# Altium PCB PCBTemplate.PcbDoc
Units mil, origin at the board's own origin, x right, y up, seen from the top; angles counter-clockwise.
Board outline 6000 x 4000 mil, 4 copper layers (Top Layer, Internal Plane 1, Internal Plane 2, Bottom Layer); 0 components, 0 nets, 1 pads, 0 vias.
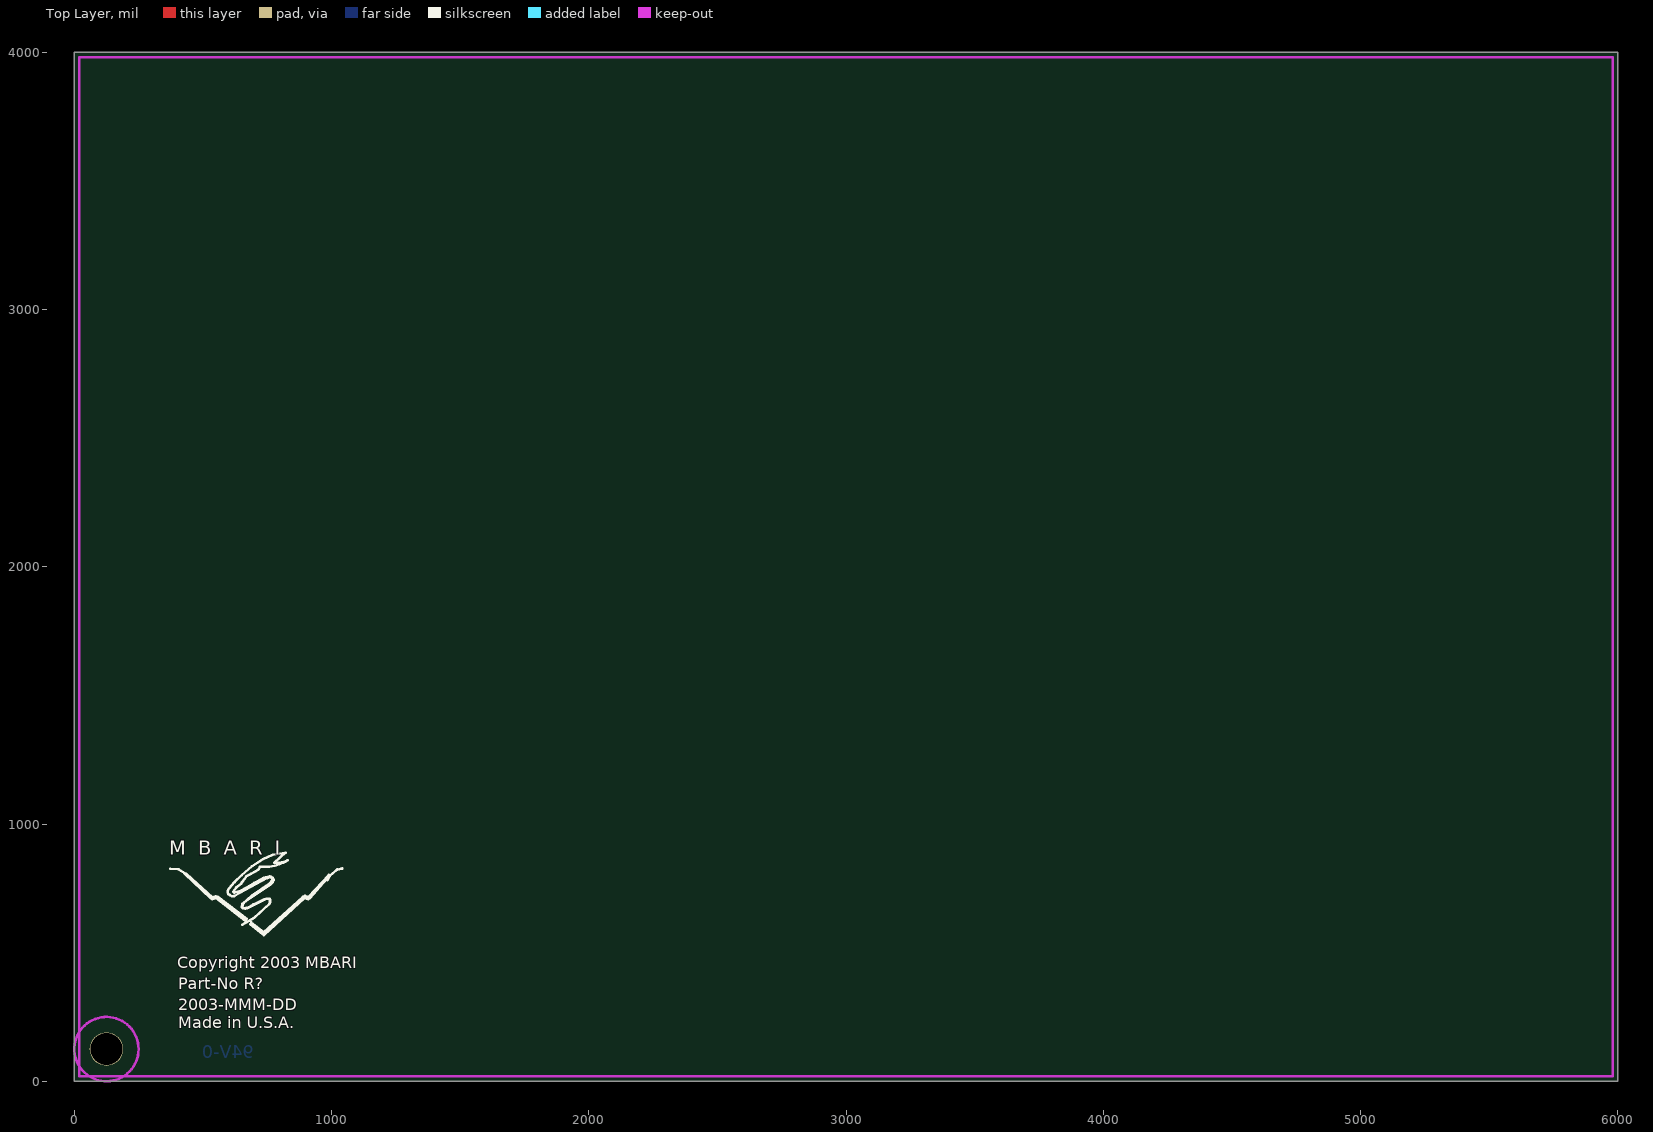
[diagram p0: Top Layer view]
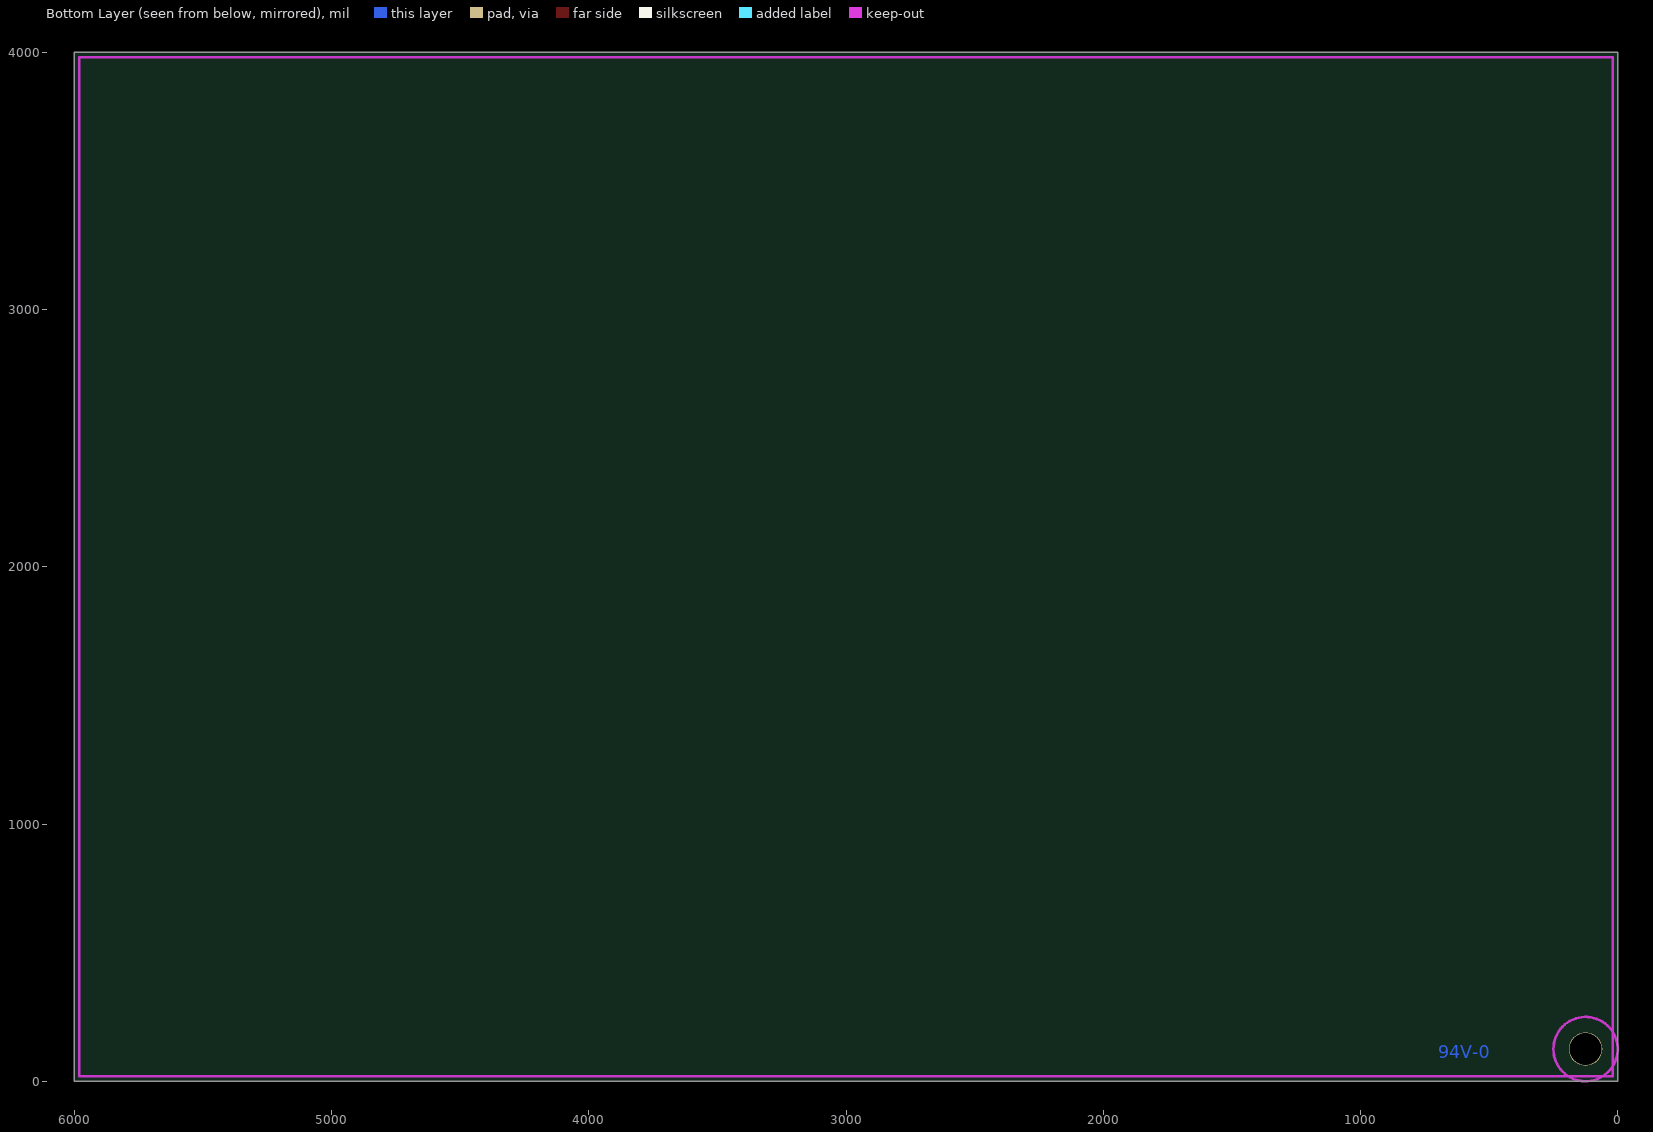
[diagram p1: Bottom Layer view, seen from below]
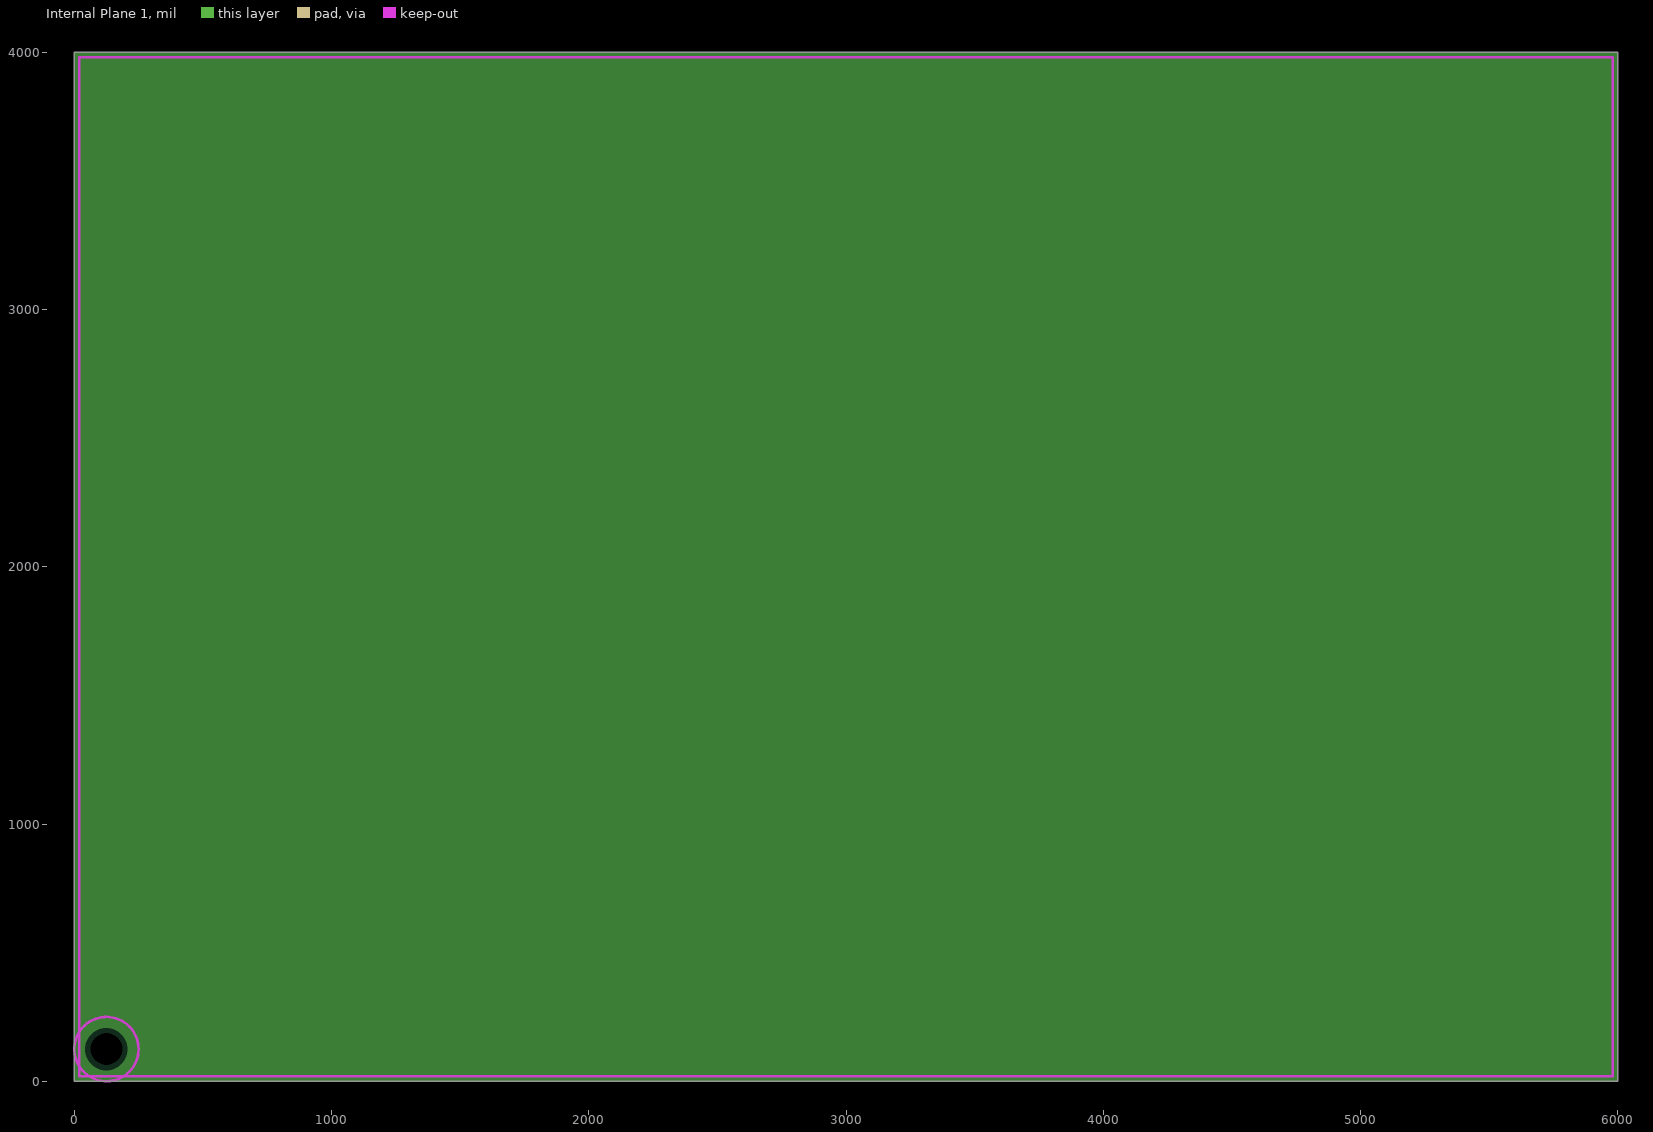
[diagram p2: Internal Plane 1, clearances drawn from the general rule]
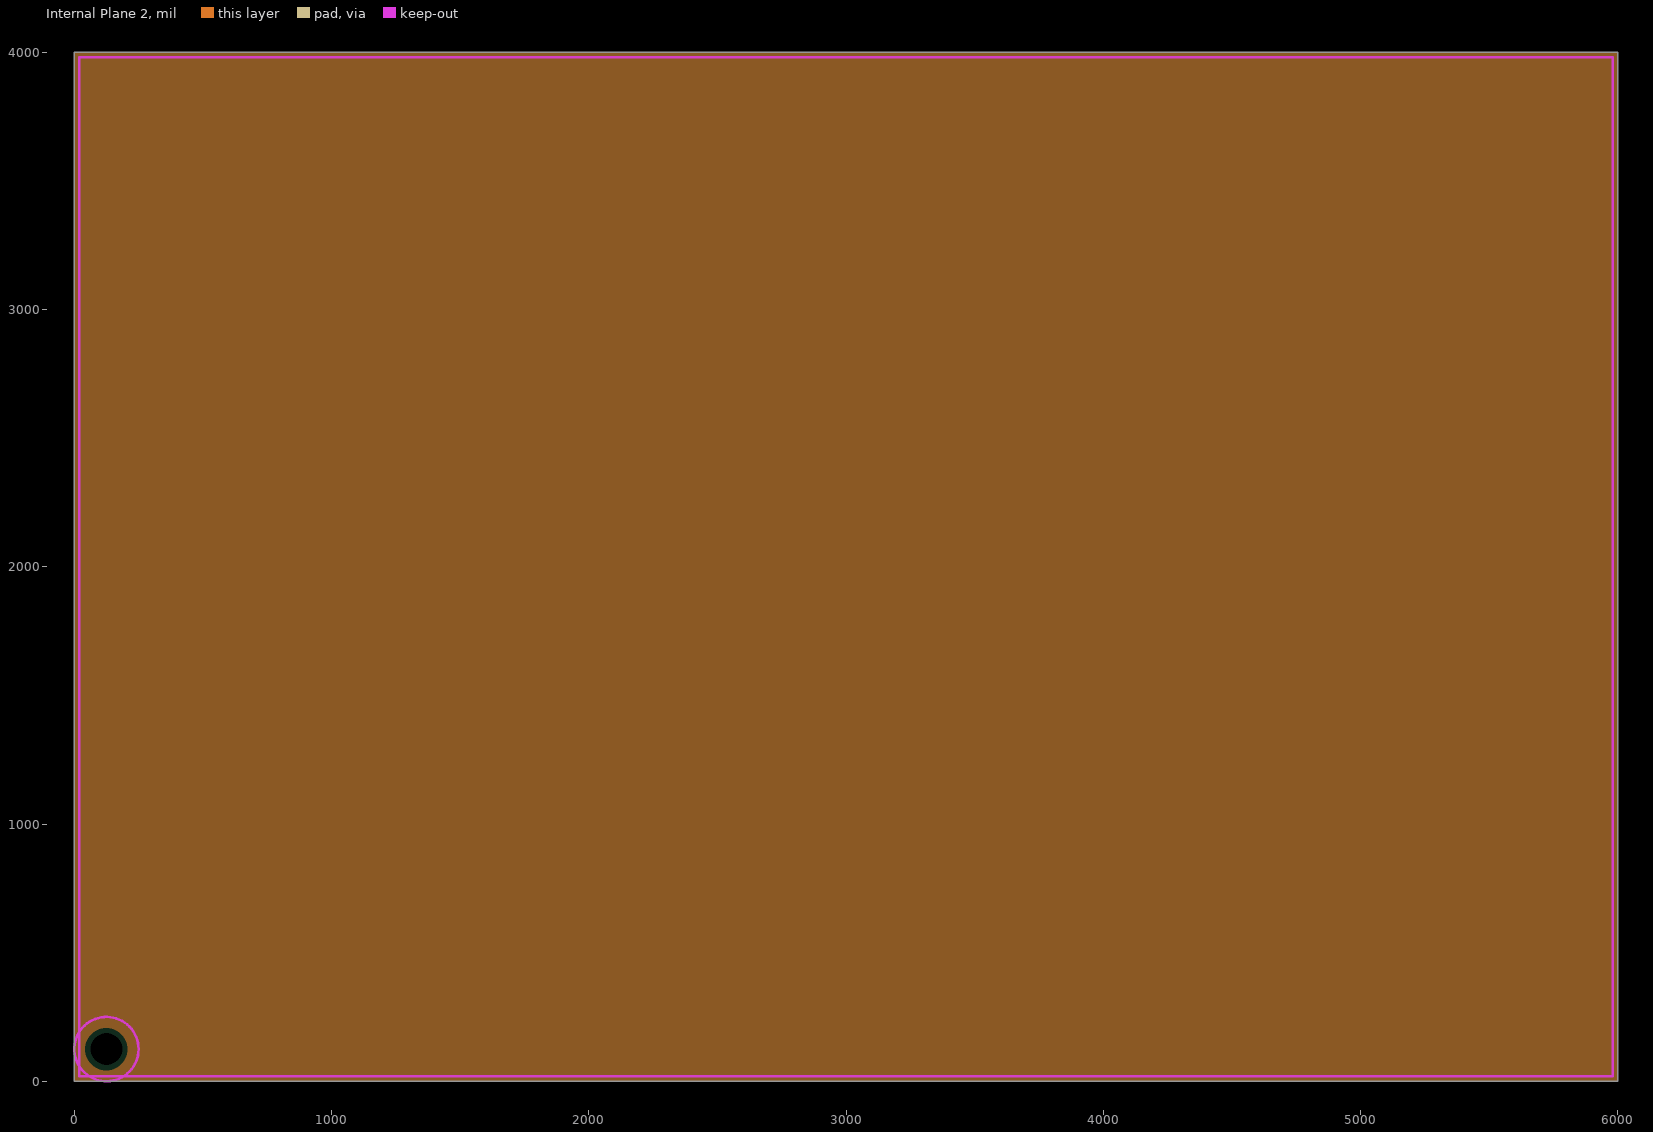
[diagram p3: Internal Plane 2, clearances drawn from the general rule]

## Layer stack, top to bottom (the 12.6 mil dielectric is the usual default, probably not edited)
Top Layer: signal copper 1.4
Dielectric: dielectric 12.6, FR-4, Dk 4.8
Internal Plane 1: plane copper 1.4
Dielectric: dielectric 12.6, FR-4, Dk 4.8
Internal Plane 2: plane copper 1.4
Dielectric: dielectric 12.6, FR-4, Dk 4.8
Bottom Layer: signal copper 1.4

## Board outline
0,0 0,4000 6000,4000 6000,0

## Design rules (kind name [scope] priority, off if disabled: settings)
Clearance [All] p1: gap=13
ComponentClearance [All] p1: gap=10 collisioncheckmode=0
FanoutControl Fanout_Small [(CompPinCount < 5)] p1: bgadir=Out bgaviamode=Centered fanoutstyle=Auto fanoutdirection=OutThenIn viagrid=1 // Fanout_Small (Default Rule)
FanoutControl Fanout_Default [All] p2: bgadir=Out bgaviamode=Centered fanoutstyle=Auto fanoutdirection=Alternating viagrid=1 // Fanout_Default (Default Rule)
FanoutControl Fanout_BGA [IsBGA] p4: bgadir=Out bgaviamode=Centered fanoutstyle=Auto fanoutdirection=Alternating viagrid=1 // Fanout_BGA (Default Rule)
FanoutControl Fanout_LCC [IsLCC] p5: bgadir=Out bgaviamode=Centered fanoutstyle=Auto fanoutdirection=Alternating viagrid=1 // Fanout_LCC (Default Rule)
HoleSize [All] p1: absolutevalues=TRUE maxlimit=152 minlimit=1 maxpercent=80.000 minpercent=20.000
PlaneClearance [All] p1: clearance=20
PlaneConnect [All] p1: planeconnectstyle=Relief reliefexpansion=20 reliefentries=4 reliefconductorwidth=10 reliefairgap=10
PolygonConnect [All] p1: connectstyle=Relief reliefconductorwidth=10 reliefentries=4 polygonreliefangle="90 Angle"
RoutingLayers [All] p1: top layer=Horizontal bottom layer=Vertical
RoutingVias [All] p1: holewidth=35 width=52 viastyle="Through Hole" minholewidth=28 minwidth=32 maxholewidth=86 maxwidth=72
SolderMaskExpansion [All] p1: expansion=4
TestPointUsage [All] p1: valid=0 allowmultiple=FALSE
Testpoint [All] p1: side=15 testpointundercomponent=TRUE minsize=40 maxsize=100 preferedsize=60 minholesize=0 maxholesize=40 preferedholesize=32 testpointgrid=1 style=1023 order=1234567890
Width [All] p1: maxlimit=250 minlimit=8 preferedwidth=12 toplayer_prefwidth=10 bottomlayer_prefwidth=10 minimp=50.000000 maximp=50.000000 favimp=50.000000
9 further rules are at their usual default settings.

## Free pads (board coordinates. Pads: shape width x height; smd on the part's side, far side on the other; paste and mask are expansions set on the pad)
  round 130 hole 125: 0(125,125)

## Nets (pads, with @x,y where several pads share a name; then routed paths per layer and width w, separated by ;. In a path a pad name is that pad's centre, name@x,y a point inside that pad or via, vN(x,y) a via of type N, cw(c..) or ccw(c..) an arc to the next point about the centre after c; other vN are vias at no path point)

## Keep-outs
Keep-Out Layer:
  circle w10: c125,125 r125
  lines w10: 20,20 5980,20 5980,3980 20,3980 20,20
  text ".GKO" at 15240,-540 h90

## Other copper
Top Layer:
  text ".GTL" at 15240,-540 h90
Bottom Layer:
  text "94V-0" at 697.07,88.79 h50
  text ".GBL" at 15240,-540 h90

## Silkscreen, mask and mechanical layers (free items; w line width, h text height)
Top Overlay:
  lines w10: 373,826 405,824 436,806 537,715 550,719 557,718 671,631 ; 428,808 531,711 ; 536,708 551,712 666,624 ; 653,608 699,635 758,689 761,696 761,706 759,709 753,710 746,710 ; 684,610 731,573 ; 688,617 736,579 888,717 897,721 911,716 990,802 993,797 1022,823 1042,827 ; 760,695 760,703 758,707 753,709 746,710 ; 894,713 909,708 ; 916,712 981,785 ; 984,782 990,791 ; 746,710 739,707 696,687 679,676 656,672 652,677 653,689 691,721 759,768 770,784 766,795 760,797 736,791 700,771 652,743 622,733 618,737 629,752 647,767 669,797 687,807 702,814 715,822 722,833 757,833 780,838 796,844 812,849 829,859 824,855 795,850 778,850 821,889 772,881 733,863 690,835 651,801 623,774 601,749 597,741 596,735 599,728 604,724 612,719 622,720 750,790 760,793 767,793 771,791 773,787 775,782 772,775 764,766 669,701 658,693 654,685 653,679 657,672 664,670 672,672 746,710 ; 737,568 896,713 737,568
  text "M  B  A  R  I" at 370,880 h55
  text "Copyright 2003 MBARI" at 400,440 h45
  text "Part-No R?" at 405,356.68 h45
  text "2003-MMM-DD" at 405,276.68 h45
  text "Made in U.S.A." at 405,206.68 h45
  text ".GTO" at 15240,-540 h90
Bottom Overlay:
  text ".GBO" at 15250,-540 h90
Top Solder:
  text ".GTS" at 15240,-540 h90
Bottom Solder:
  text ".GBS" at 15240,-540 h90
Drill Guide:
  text ".GG1" at 15450,-540 h90
Mechanical 4:
  the board outline again, w10
Mechanical 16:
  lines w5: -800,1750 -600,1750 ; -800,4500 -600,4500 ; -800,7250 -600,7250 ; 2035,-800 2035,-600 ; 2035,9600 2035,9795 ; 4865,-800 4865,-600 ; 4865,9600 4865,9795 ; 7700,-800 7700,-600 ; 7700,9600 7700,9795 ; 9700,0 15600,0 ; 10530,-800 10530,-600 ; 10530,9600 10530,9795 ; 11100,-300 15600,-300 ; 11100,300 12600,300 ; 12600,-600 12600,0 12600,600 ; 13365,-800 13365,-600 ; 13365,9600 13365,9795 ; 14700,-600 14700,0 ; 15600,1750 15795,1750 ; 15600,4500 15795,4500 ; 15600,7250 15795,7250 ; 11100,-600 9700,-600 9700,600 11100,600 ; 11100,-600 15600,-600 ; 11100,-600 11100,600 ; 11100,600 12600,600 ; 12600,600 15600,600 15600,-600 ; 15600,-600 -600,-600 -600,9600 15600,9600 15600,-600 ; -800,-800 -800,9795 15795,9795 15795,-800 -800,-800
  lines w10: 10033,446 10065,444 10096,426 10197,335 10210,339 10217,338 10331,251 ; 10088,428 10191,331 ; 10196,328 10211,332 10326,244 ; 10313,228 10359,255 10418,309 10421,316 10421,326 10419,329 10413,330 10406,330 ; 10344,230 10391,193 ; 10348,237 10396,199 10548,337 10557,341 10571,336 10650,422 10653,417 10682,443 10702,447 ; 10420,315 10420,323 10418,327 10413,329 10406,330 ; 10554,333 10569,328 ; 10576,332 10641,405 ; 10644,402 10650,411 ; 10406,330 10399,327 10356,307 10339,296 10316,292 10312,297 10313,309 10351,341 10419,388 10430,404 10426,415 10420,417 10396,411 10360,391 10312,363 10282,353 10278,357 10289,372 10307,387 10329,417 10347,427 10362,434 10375,442 10382,453 10417,453 10440,458 10456,464 10472,469 10489,479 10484,475 10455,470 10438,470 10481,509 10432,501 10393,483 10350,455 10311,421 10283,394 10261,369 10257,361 10256,355 10259,348 10264,344 10272,339 10282,340 10410,410 10420,413 10427,413 10431,411 10433,407 10435,402 10432,395 10424,386 10329,321 10318,313 10314,305 10313,299 10317,292 10324,290 10332,292 10406,330 ; 10397,188 10556,333 10397,188
  text "1" at 601.34,9665 h70
  text "2" at 3427,9665 h70
  text "3" at 6252,9665 h70
  text "4" at 9093.01,9665 h70
  text "5" at 11927,9665 h70
  text "6" at 14762,9665 h70
  text "A" at -725,8622 h70
  text "A" at 15675,8622 h70
  text "B" at -725,5888.02 h70
  text "B" at 15675,5888.02 h70
  text "C" at -725,3107 h70
  text "C" at 15675,3107 h70
  text "M  B  A  R  I" at 10030,500 h55
  text "ENGINEER:" at 11150,500 h45
  text "TITLE:" at 12650,500 h45
  text "Mark Sibenac" at 11660,470 h70
  text "Title I" at 13000,380 h90
  text "1 831 775 2028" at 11650,330 h60
  text "D" at -725,285 h70
  text "D" at 15675,285 h70
  text "PCB DESIGNER:" at 11150,205 h45
  text "Title II" at 13020,160 h90
  text "Copyright      2003" at 9880,150 h60
  text "Monterey Bay Aquarium Research Institute" at 9750,40 h45
  text "DATE:" at 11150,-100 h45
  text "PART NO.:" at 12650,-100 h45
  text "REV:" at 14750,-100 h45
  text ".PRINT_DATE" at 11200,-220 h70
  text "1" at 15030,-220 h90
  text "Part Number" at 13010,-230 h60
  text "M.B.A.R.I." at 9780,-240 h100
  text "7700 Sandholdt Rd." at 9770,-340 h60
  text "FILE NAME:" at 11150,-400 h45
  text "DWG NO:" at 12650,-400 h45
  text "GERBER:" at 14750,-400 h45
  text "Moss Landing, CA 95039" at 9770,-450 h60
  text "DWG Number" at 13010,-490 h60
  text ".PCB_FILE_NAME_NO_PATH" at 11200,-520 h70
  text ".GM16" at 14860,-530 h70
  text "Fax: 1 831 775 1646" at 9770,-550 h60
  text "1" at 601.34,-735 h70
  text "2" at 3427,-735 h70
  text "3" at 6252,-735 h70
  text "4" at 9093.01,-735 h70
  text "5" at 11927,-735 h70
  text "6" at 14762,-735 h70
Drill Drawing:
  text ".LEGEND" at 9945,870 h60
  text "Drill Drawing." at 9925,780 h60
  text ".GD1" at 15445,-540 h90

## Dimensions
0,0 to 6000,0 on Mechanical 4
0,4000 to 0,0 on Mechanical 4
125,125 to 0,0 on Mechanical 4
125,125 to 0,0 on Mechanical 4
